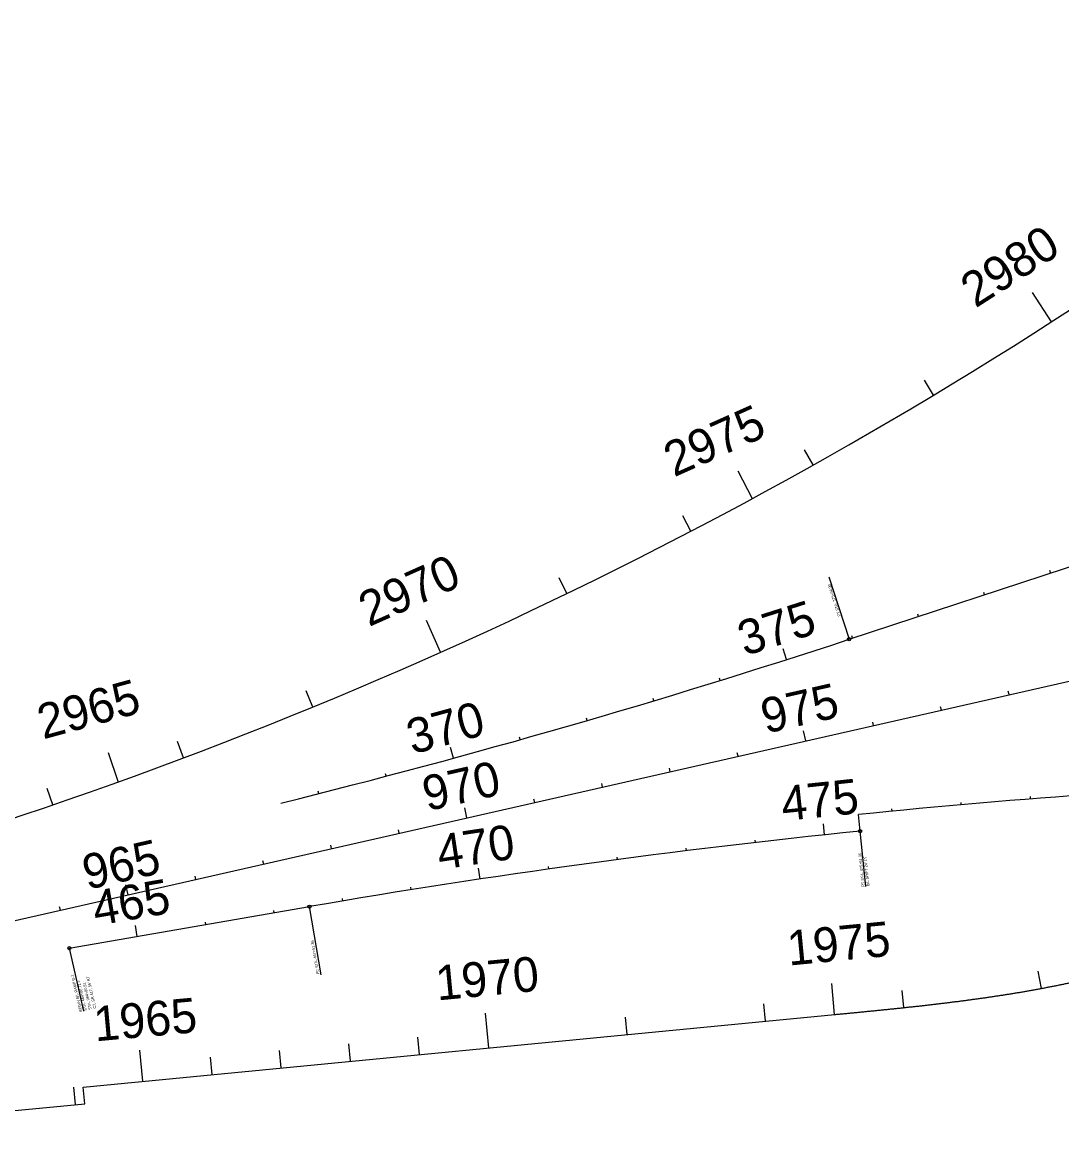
# Model space of a CAD drawing. Extents: x 448091 to 665917, y 1461380 to 1587607.
# Drawn here: x 554394 to 555890, y 1466290 to 1467879 of the extents above; entities that cross this region are included whole.
import ezdxf

# ---------------------------------------------------------------- set-up
doc = ezdxf.new("R2010")
doc.units = 0
for name, color, linetype in [('AttenuatorTM', 7, 'Continuous'), ('Barricade3', 7, 'Continuous'), ('Barricade4', 7, 'Continuous'), ('TextShtNo', 7, 'Continuous'), ('TextTitle', 7, 'Continuous')]:
    doc.layers.add(name, color=color, linetype=linetype)

msp = doc.modelspace()

# ---------------------------------------------------------------- linework, layer by layer
at = {"layer": 'AttenuatorTM'}
for p, q in [((555555, 1467080.6), (555584.5, 1466991)), ((555608.1, 1466635.6), (555600, 1466714.9)), ((554824.7, 1466508.1), (554807.7, 1466606.4)), ((554482.8, 1466455.9), (554462.2, 1466546.7))]:
    msp.add_line(p, q, dxfattribs=at)
for centre in [(555584.3, 1466991), (555600, 1466714.9), (554807.7, 1466606.4), (554462.1, 1466546.7)]:
    msp.add_circle(centre, 2.26, dxfattribs=at)
at = {"layer": 'Barricade3'}
for p, q in [((555875.2, 1467447.6), (555848.2, 1467489.6)), ((555705.4, 1467342), (555692.5, 1467363.4)), ((555532.4, 1467241.6), (555520.2, 1467263.4)), ((555445.2, 1467192.7), (555424.4, 1467232.6)), ((555356.5, 1467146.4), (555344.9, 1467168.6)), ((555874.2, 1467086.3), (555873.1, 1467089.7)), ((555177.8, 1467056.7), (555166.9, 1467079.2)), ((555779.2, 1467055.1), (555778.1, 1467058.4)), ((555684.2, 1467023.8), (555683.1, 1467027.2)), ((554996.4, 1466972.3), (554976, 1467018)), ((555589.2, 1466992.6), (555588.1, 1466996)), ((555494.1, 1466961.7), (555489.2, 1466977)), ((555398.7, 1466931.7), (555397.6, 1466935.1)), ((554812.6, 1466893.5), (554803.1, 1466916.7)), ((555814.5, 1466911.3), (555813.3, 1466916.2)), ((555303.1, 1466902.5), (555302, 1466905.9)), ((555716.9, 1466889.2), (555715.8, 1466894)), ((555207.2, 1466874.1), (555206.2, 1466877.5)), ((555619.4, 1466867), (555618.3, 1466871.9)), ((555521.9, 1466844.9), (555518.6, 1466859.5)), ((554626.5, 1466820.3), (554617.7, 1466843.7)), ((555014.7, 1466819.9), (555010.4, 1466835.4)), ((555111, 1466846.6), (555110.1, 1466850)), ((554532.9, 1466785.1), (554518.3, 1466827.7)), ((555424.4, 1466822.7), (555423.3, 1466827.6)), ((555326.9, 1466800.5), (555325.8, 1466805.4)), ((554918, 1466794.1), (554917.1, 1466797.5)), ((554438.3, 1466752.8), (554430.2, 1466776.5)), ((554821.2, 1466769.1), (554820.4, 1466772.5)), ((555229.4, 1466778.4), (555228.3, 1466783.3)), ((554438.3, 1466752.9), (554437.2, 1466756.2)), ((555131.8, 1466756.2), (555130.7, 1466761.1)), ((555745.6, 1466752.8), (555745.3, 1466756.4)), ((555845.2, 1466761.2), (555845, 1466764.8)), ((555034.3, 1466734.1), (555031, 1466748.7)), ((555646, 1466743.6), (555645.7, 1466747.1)), ((555549, 1466709.6), (555547.3, 1466725.6)), ((554936.8, 1466711.9), (554935.7, 1466716.8)), ((554839.3, 1466689.8), (554838.2, 1466694.6)), ((555449.6, 1466698.6), (555449.2, 1466702.1)), ((555251.1, 1466674.1), (555250.6, 1466677.6)), ((555350.3, 1466686.8), (555349.8, 1466690.3)), ((554741.8, 1466667.6), (554740.7, 1466672.5)), ((555053.1, 1466646), (555050.7, 1466661.9)), ((555152, 1466660.5), (555151.5, 1466664)), ((554644.3, 1466645.5), (554643.2, 1466650.3)), ((554546.8, 1466623.3), (554543.4, 1466637.9)), ((554954.2, 1466630.7), (554953.7, 1466634.2)), ((554855.6, 1466614.5), (554855, 1466618)), ((554449.2, 1466601.2), (554448.1, 1466606)), ((554757, 1466597.6), (554756.4, 1466601.1)), ((554658.5, 1466580.6), (554657.9, 1466584.1)), ((554559.9, 1466563.6), (554557.2, 1466579.4)), ((555860.9, 1466488.8), (555856.3, 1466513.4)), ((555563.4, 1466451.2), (555559.1, 1466496)), ((555662.9, 1466461.2), (555660.3, 1466486)), ((555065.7, 1466403.2), (555060.9, 1466453)), ((555463.9, 1466441.6), (555461.5, 1466466.5)), ((555264.8, 1466422.4), (555262.4, 1466447.3)), ((554866.6, 1466384), (554864.2, 1466408.9)), ((554966.2, 1466393.6), (554963.8, 1466418.5)), ((554568, 1466355.2), (554563.7, 1466400)), ((554667.6, 1466364.8), (554665.2, 1466389.7)), ((554767.1, 1466374.4), (554764.7, 1466399.3)), ((554470.8, 1466321.7), (554468.4, 1466346.6))]:
    msp.add_line(p, q, dxfattribs=at)
at = {"layer": 'Barricade4'}
for p, q in [((554032.5, 1466506.5), (560072.1, 1467878.6)), ((555584.3, 1466991), (556616.2, 1467330.3)), ((555600, 1466714.9), (555597.6, 1466738.8)), ((554462.1, 1466546.7), (554807.6, 1466606.4)), ((554482.2, 1466346.9), (555563.6, 1466451.3)), ((554482.2, 1466346.9), (555563.6, 1466451.3)), ((554484.5, 1466323), (554482.2, 1466346.9)), ((554138.3, 1466289.6), (554484.5, 1466323)), ((554138.3, 1466289.6), (554484.5, 1466323))]:
    msp.add_line(p, q, dxfattribs=at)
for centre, radius, start, end in [((552300.1, 1473008.5), 6611.1, 267.58572, 305.78004), ((552004.7, 1477876.7), 11459.2, 283.945, 288.20306), ((556757.9, 1455314.4), 11483.2, 92.3025, 95.79917), ((556757.9, 1455314.4), 11459.2, 95.79917, 99.79917)]:
    msp.add_arc(centre, radius, start, end, dxfattribs=at)
msp.add_spline([(555563.6, 1466451.3), (555569, 1466451.8), (555574.4, 1466452.3), (555579.8, 1466452.8), (555585.1, 1466453.3), (555590.5, 1466453.9), (555595.9, 1466454.4), (555601.3, 1466454.9), (555606.7, 1466455.4), (555612, 1466456), (555617.4, 1466456.5), (555622.8, 1466457), (555628.2, 1466457.6), (555633.5, 1466458.1), (555638.9, 1466458.7), (555644.3, 1466459.2), (555649.7, 1466459.8), (555655.1, 1466460.3), (555660.4, 1466460.9), (555665.8, 1466461.5), (555671.2, 1466462.1), (555676.6, 1466462.6), (555681.9, 1466463.2), (555687.3, 1466463.8), (555692.7, 1466464.4), (555698, 1466465.1), (555703.4, 1466465.7), (555708.8, 1466466.3), (555714.1, 1466466.9), (555719.5, 1466467.6), (555724.9, 1466468.2), (555730.2, 1466468.9), (555735.6, 1466469.6), (555741, 1466470.2), (555746.3, 1466470.9), (555751.7, 1466471.6), (555757, 1466472.4), (555762.4, 1466473.1), (555767.8, 1466473.8), (555773.1, 1466474.6), (555778.5, 1466475.3), (555783.8, 1466476.1), (555789.2, 1466476.9), (555794.5, 1466477.7), (555799.9, 1466478.5), (555805.2, 1466479.3), (555810.5, 1466480.1), (555815.9, 1466481), (555821.2, 1466481.9), (555826.5, 1466482.7), (555831.9, 1466483.6), (555837.2, 1466484.6), (555842.5, 1466485.5), (555847.9, 1466486.4), (555853.2, 1466487.4), (555858.5, 1466488.4), (555863.8, 1466489.3), (555869.1, 1466490.4), (555874.4, 1466491.4), (555879.7, 1466492.4), (555885, 1466493.5), (555890.3, 1466494.6), (555895.6, 1466495.7), (555900.9, 1466496.8), (555906.2, 1466497.9), (555911.5, 1466499.1), (555916.7, 1466500.3), (555922, 1466501.5), (555927.3, 1466502.7), (555932.5, 1466503.9), (555937.8, 1466505.2), (555943.1, 1466506.4), (555948.3, 1466507.7), (555953.5, 1466509.1), (555958.8, 1466510.4)], degree=3, dxfattribs=at)
at = {"layer": 'TextShtNo'}
for p, q in [((554032.5, 1466506.5), (560072.1, 1467878.6)), ((555584.3, 1466991), (556616.2, 1467330.3)), ((555600, 1466714.9), (555597.6, 1466738.8)), ((554462.1, 1466546.7), (554807.6, 1466606.4))]:
    msp.add_line(p, q, dxfattribs=at)
for centre, radius, start, end in [((552004.7, 1477876.7), 11459.2, 283.945, 288.20306), ((556757.9, 1455314.4), 11483.2, 92.3025, 95.79917), ((556757.9, 1455314.4), 11459.2, 95.79917, 99.79917)]:
    msp.add_arc(centre, radius, start, end, dxfattribs=at)
at = {"layer": 'TextTitle'}
for p, q in [((555874.2, 1467086.3), (555873.1, 1467089.7)), ((555779.2, 1467055.1), (555778.1, 1467058.4)), ((555684.2, 1467023.8), (555683.1, 1467027.2)), ((555589.2, 1466992.6), (555588.1, 1466996)), ((555494.1, 1466961.7), (555489.2, 1466977)), ((555398.7, 1466931.7), (555397.6, 1466935.1)), ((555814.5, 1466911.3), (555813.3, 1466916.2)), ((555303.1, 1466902.5), (555302, 1466905.9)), ((555716.9, 1466889.2), (555715.8, 1466894)), ((555207.2, 1466874.1), (555206.2, 1466877.5)), ((555619.4, 1466867), (555618.3, 1466871.9)), ((555521.9, 1466844.9), (555518.6, 1466859.5)), ((555014.7, 1466819.9), (555010.4, 1466835.4)), ((555111, 1466846.6), (555110.1, 1466850)), ((555424.4, 1466822.7), (555423.3, 1466827.6)), ((555326.9, 1466800.5), (555325.8, 1466805.4)), ((554918, 1466794.1), (554917.1, 1466797.5)), ((554821.2, 1466769.1), (554820.4, 1466772.5)), ((555229.4, 1466778.4), (555228.3, 1466783.3)), ((555131.8, 1466756.2), (555130.7, 1466761.1)), ((555745.6, 1466752.8), (555745.3, 1466756.4)), ((555845.2, 1466761.2), (555845, 1466764.8)), ((555034.3, 1466734.1), (555031, 1466748.7)), ((555646, 1466743.6), (555645.7, 1466747.1)), ((555549, 1466709.6), (555547.3, 1466725.6)), ((554936.8, 1466711.9), (554935.7, 1466716.8)), ((554839.3, 1466689.8), (554838.2, 1466694.6)), ((555449.6, 1466698.6), (555449.2, 1466702.1)), ((555251.1, 1466674.1), (555250.6, 1466677.6)), ((555350.3, 1466686.8), (555349.8, 1466690.3)), ((554741.8, 1466667.6), (554740.7, 1466672.5)), ((555053.1, 1466646), (555050.7, 1466661.9)), ((555152, 1466660.5), (555151.5, 1466664)), ((554644.3, 1466645.5), (554643.2, 1466650.3)), ((554546.8, 1466623.3), (554543.4, 1466637.9)), ((554954.2, 1466630.7), (554953.7, 1466634.2)), ((554855.6, 1466614.5), (554855, 1466618)), ((554449.2, 1466601.2), (554448.1, 1466606)), ((554757, 1466597.6), (554756.4, 1466601.1)), ((554658.5, 1466580.6), (554657.9, 1466584.1)), ((554559.9, 1466563.6), (554557.2, 1466579.4))]:
    msp.add_line(p, q, dxfattribs=at)

# ---------------------------------------------------------------- texts
at = {"layer": 'AttenuatorTM'}
for s, rotation, p in [('PT STA. 375+94.90', 107.9417, (555572.2, 1467024.5)), ('PT STA. 475+51.36', 95.7936, (555606.5, 1466635.3)), ("B/L SHIFT 24' LT", 95.7936, (555613.5, 1466636)), ('PC STA. 467+51.36', 99.8236, (554821.9, 1466509.5)), ('BEGIN B/L RAMP B-2', 102.8583, (554480.5, 1466455.6)), ("C/L SR 417, 56' RT", 102.8583, (554501, 1466460.3)), ('STA. 464+00.72 =', 102.8583, (554487.4, 1466457.2)), ('STA. 964+00.51', 102.8583, (554494.2, 1466458.7))]:
    msp.add_text(s, height=4, rotation=rotation, dxfattribs=at).set_placement(p)
at = {"layer": 'Barricade3'}
for s, rotation, p in [('2980', 32.7368, (555766.1, 1467466.6)), ('2975', 24.0701, (555332.2, 1467223.7)), ('2970', 24.0701, (554893.2, 1467008.4)), ('375', 17.7286, (555434, 1466966.5)), ('2965', 15.4034, (554424.5, 1466846.8)), ('975', 12.7996, (555464, 1466855.1)), ('370', 15.2285, (554955.8, 1466825.2)), ('970', 12.7996, (554977, 1466743.5)), ('475', 6.056, (555489.1, 1466729.3)), ('470', 8.556, (554995.2, 1466659.3)), ('965', 12.7996, (554487.7, 1466630.5)), ('465', 9.7992, (554500.2, 1466578.7)), ('1975', 5.5116, (555497.5, 1466521.6)), ('1970', 5.5116, (554991.7, 1466471.4)), ('1965', 5.1817, (554499.5, 1466412.6))]:
    msp.add_text(s, height=50, rotation=rotation, dxfattribs=at).set_placement(p)
at = {"layer": 'TextTitle'}
for s, rotation, p in [('375', 17.7286, (555434, 1466966.5)), ('975', 12.7996, (555464, 1466855.1)), ('370', 15.2285, (554955.8, 1466825.2)), ('970', 12.7996, (554977, 1466743.5)), ('475', 6.056, (555489.1, 1466729.3)), ('470', 8.556, (554995.2, 1466659.3)), ('965', 12.7996, (554487.7, 1466630.5)), ('465', 9.7992, (554500.2, 1466578.7))]:
    msp.add_text(s, height=50, rotation=rotation, dxfattribs=at).set_placement(p)

doc.saveas('drawing.dxf')
